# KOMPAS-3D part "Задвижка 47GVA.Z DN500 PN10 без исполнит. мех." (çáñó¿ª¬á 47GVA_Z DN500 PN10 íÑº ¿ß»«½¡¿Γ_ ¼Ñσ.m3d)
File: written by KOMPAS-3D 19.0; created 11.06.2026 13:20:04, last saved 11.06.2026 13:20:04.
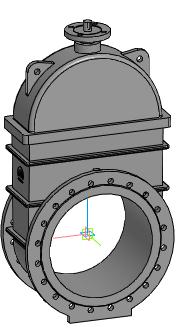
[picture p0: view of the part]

Document properties: Автор: Евгений; Полное имя файла: Z:\3.Личные\kachalov\001_3d для проектировщиков\2.2 Тип 47GVA, 47GVA.Z\_stp\_stp_Задвижка 47GVA.Z DN350-DN1200 без исп.мех\Задвижка 47GVA_Z DN500 PN10 без исполнит_ мех.m3d

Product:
- Part/product: Задвижка 47GVA.Z DN500 PN10 без исполнит. мех.

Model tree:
1. Операция без истории:1  (labels: Задвижка 47GVA.Z DN500 PN10 без исполнит. мех.)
